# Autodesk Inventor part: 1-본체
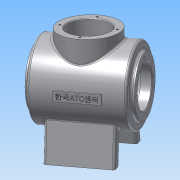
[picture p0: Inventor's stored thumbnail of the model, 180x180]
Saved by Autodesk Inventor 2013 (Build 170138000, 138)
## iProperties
Created: 2015-01
Part Number: 1-본체
Material: 알루미늄 6061
Document SubType Name: Modeling
Designer: Administrator
Density: 2.71 g/cm^3
Mass: 1021.7 g
Surface Area: 1061.52 cm^2
Volume: 377.013 cm^3
Author: Administrator
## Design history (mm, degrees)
sketch "스케치1"
  geometry: C1 r 50 at (0, 0); 1 further point
  constraints: 1 centre point, 1 coincident
  dimensions: "d0" = 100 diameter of C1
extrude "돌출1" new body sketch "스케치1" stored distance "d2" = 112; taper "d3" = 0 deg
sketch "스케치2"
  geometry: C1 r 38 at (0, 0); 1 further point
  constraints: 1 centre point, 1 coincident
  dimensions: "d4" = 76 diameter of C1
extrude "돌출2" join sketch "스케치2" distance "d6" = 5; taper "d7" = 0 deg
sketch "스케치3"
  geometry: C1 r 38 at (0, 0); 1 further point
  constraints: 1 centre point, 1 coincident
  dimensions: "d8" = 76 diameter of C1
extrude "돌출3" join sketch "스케치3" distance "d10" = 5; taper "d11" = 0 deg
node "작업 평면2"
sketch "스케치4"
  geometry: C1 r 38 at (0, 0); 1 further point
  constraints: 1 centre point, 1 coincident
  dimensions: "d13" = 76 diameter of C1
extrude "돌출4" join sketch "스케치4" stored distance "d15" = 5; taper "d16" = 0 deg
sketch "스케치6"
  geometry: L1 (20, 37.42)-(80, 48); L2 (80, 48)-(80, 34); L3 (80, 34)-(20, 23.42); L4 (20, 23.42)-(20, 37.42); L5 (0, 0)-(70, 0); L6 (80, -48)-(80, -34); L7 (80, -34)-(20, -23.42); L8 (20, -37.42)-(80, -48); L9 (20, -23.42)-(20, -37.42)
  constraints: 18 end point, 4 symmetric about line, 2 parallel, 1 perpendicular, 1 vertical
  dimensions: "d27" = 14 distance of L1.end L2.end; "d29" = 100 deg angle of L2 L1; "d31" = 96 diameter of L1.end L5; "d32" = 60 distance between parallel lines of L4 L2; "d33" = 80 distance from line of L5.start L2; "d34" = 10 distance from line of L5.end L2
extrude "돌출5" join sketch "스케치6" stored distance "d35" = 80; taper "d36" = 0 deg
sketch "스케치7"
  geometry: L1 (38, 61)-(-38, 61) reference; L2 (-38, -61)-(38, -61) reference; L3 (0, 61)-(0, -61); L4 (27, 61)-(27, 49); L5 (27, 49)-(45, 49); L6 (45, 49)-(45, -48); L7 (45, -48)-(27, -48); L8 (27, -48)-(27, -61); L9 (27, 61)-(0, 61); L10 (27, -61)-(0, -61); L11 (50, 56)-(-50, 56) reference; L12 (-50, -56)-(50, -56) reference; 1 further point
  constraints: 16 end point, 3 collinear, 3 parallel, 2 midpoint, 2 perpendicular, 2 point on line
  dimensions: "d38" = 90 diameter of L6 L3; "d40" = 54 diameter of L4 L3; "d99" = 7 distance between parallel lines of L5 L11; "d100" = 8 distance between parallel lines of L12 L7
revolve "회전1" sketch "스케치7" stored, may be unused: angle "d43" = 90 deg
hole "구멍1" diameter "d46" = 54; stored, may be unused: countersink angle "d50" = 90 deg, drill point angle "d52" = 0 deg; dims "d44" = 10, "d45" = 10, "d47" = 6, "d48" = 4, "d49" = 2, "d51" = 8
sketch "스케치8"
  geometry: 2 further points
  constraints: 1 horizontal alignment
  dimensions: "d53" = 32 distance of point (0, 0) point (-32, 0)
hole "구멍2" sketch "스케치8" at (-32, 0) diameter "d54" = 3.242; stored, may be unused: countersink angle "d58" = 90 deg, drill point angle "d60" = 118 deg; dims "d55" = 8, "d56" = 4, "d57" = 2, "d59" = 10
sketch "스케치9"
  geometry: 2 further points
  constraints: 1 horizontal alignment
  dimensions: "d64" = 32 distance of point (0, 0) point (-32, 0)
hole "구멍3" sketch "스케치9" at (-32, 0) diameter "d65" = 3.242; stored, may be unused: countersink angle "d69" = 90 deg, drill point angle "d71" = 118 deg; dims "d66" = 8, "d67" = 4, "d68" = 2, "d70" = 10
sketch "스케치10"
  geometry: 2 further points
  dimensions: "d75" = 32 distance of point (0, 0) point (32, 0)
hole "구멍4" sketch "스케치10" at (32, 0) diameter "d76" = 3.242; stored, may be unused: countersink angle "d80" = 90 deg, drill point angle "d82" = 118 deg; dims "d77" = 8, "d78" = 4, "d79" = 2, "d81" = 10
node "작업 평면4"
sketch "스케치12"
  geometry: L1 (-6, 26)-(6, 26); L2 (6, 26)-(6, -28); L3 (6, -28)-(-6, -28); L4 (-6, -28)-(-6, 26); L5 (38, 61)-(-38, 61) reference; 3 further points
  constraints: 8 end point, 3 midpoint, 2 parallel, 1 horizontal, 1 perpendicular, 1 vertical alignment
  dimensions: "d87" = 12 distance of L1.start L1.end; "d89" = 54 distance of L1.end L2.end; "d101" = 62 distance from line of point (6, -1) L5
extrude "돌출6" join sketch "스케치12" stored distance "d90" = 80; taper "d91" = 0 deg
sketch "스케치13"
  geometry: L1 (38, 61)-(-38, 61) reference; 2 further points
  constraints: 1 midpoint, 1 vertical alignment, 1 other
  dimensions: "d102" = 62 distance from line of point (0, -1) L1
feature "엠보싱1" sketch "스케치13" dims "d92" = 0.5, "d93" = 0
fillet "모깎기1" dims "d94" = 3
fillet "모깎기2" dims "d95" = 3
chamfer "모따기1" distance "d96" = 1; stored, may be unused: second distance "d97" = 2, angle "d98" = 45 deg
node "솔리드1"
pattern_circular "원형 패턴1" dims angle "d62" = 360 deg
pattern_circular "원형 패턴2" dims angle "d73" = 360 deg
pattern_circular "원형 패턴3" dims angle "d84" = 360 deg
other parameters: "d12" = -62, "d86" = 52
